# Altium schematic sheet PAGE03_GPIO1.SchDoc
size 381 x 304 mm; SheetNumber: 4; SheetTotal: 28
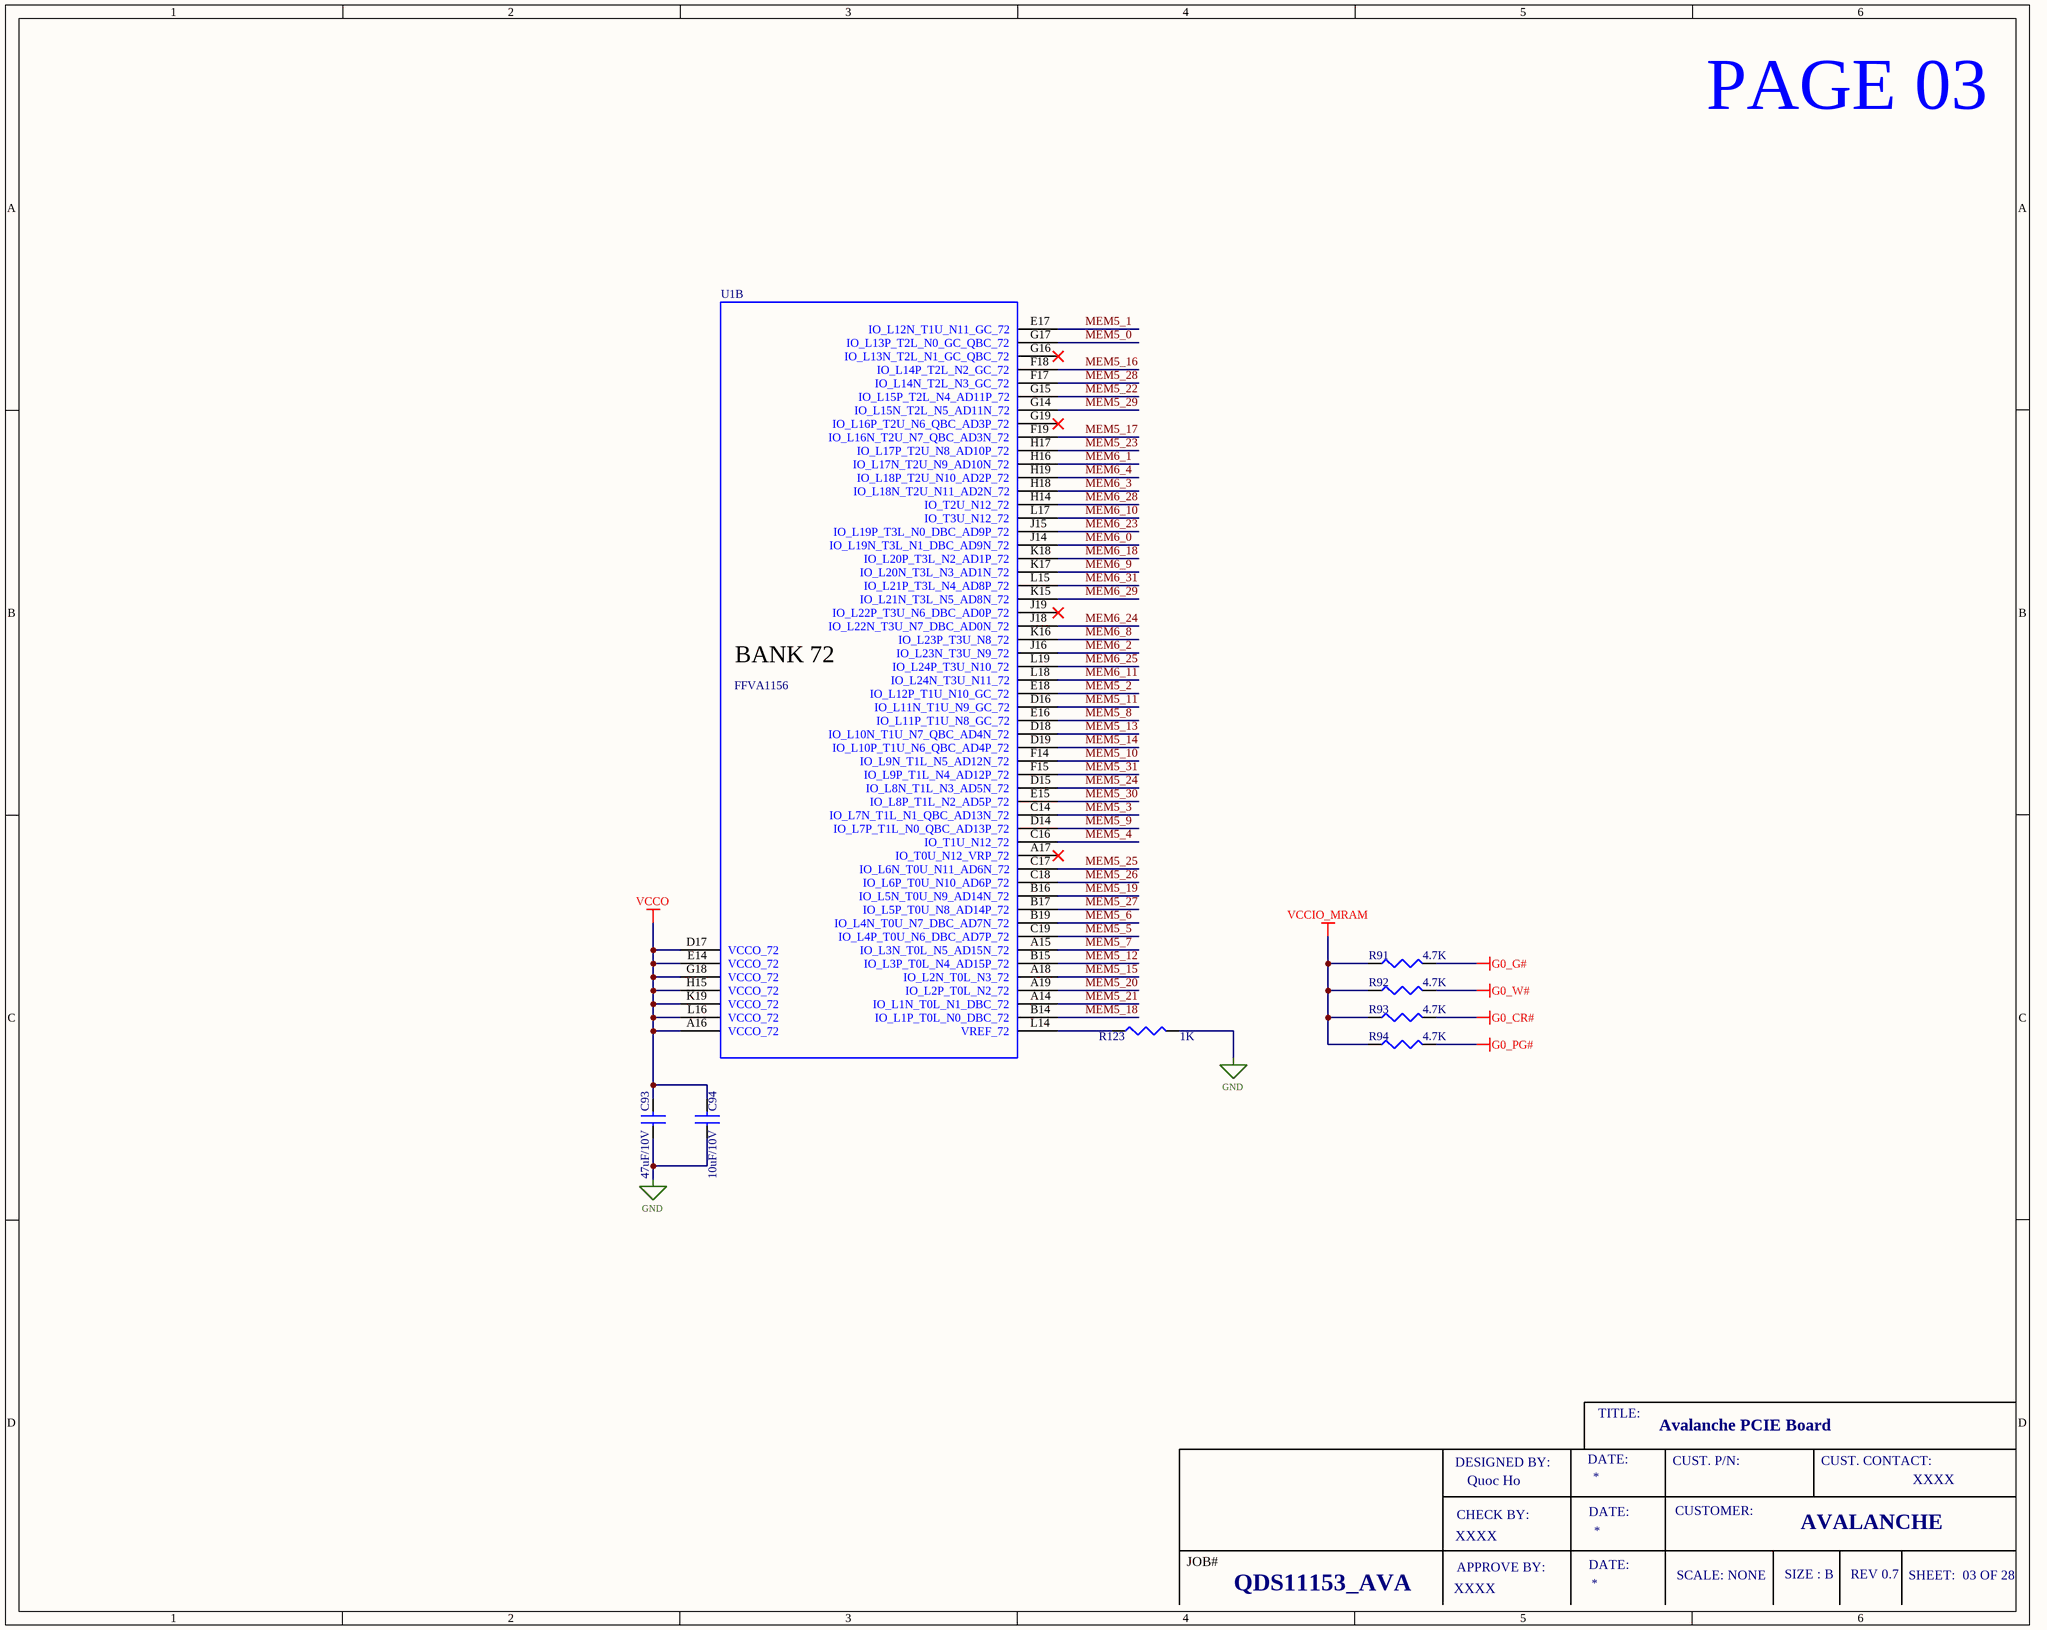
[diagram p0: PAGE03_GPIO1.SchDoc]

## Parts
C93  47uF/10V  [CN_0805]
C94  10uF/10V  [CN_0402]
R91  4.7K  [RN_0402]
R92  4.7K  [RN_0402]
R93  4.7K  [RN_0402]
R94  4.7K  [RN_0402]
R123  1K  [RN_0402]
U1  FFVA1156  [FFVA1156]  (part B of 25)

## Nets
G0_CR#: R93.2
G0_G#: R91.2
G0_PG#: R94.2
G0_W#: R92.2
GND: C93.1 C94.1 R123.2
VCCIO_MRAM: R91.1 R92.1 R93.1 R94.1
VCCO: C93.2 C94.2 U1.A16(VCCO_72) U1.D17(VCCO_72) U1.E14(VCCO_72) U1.G18(VCCO_72) U1.H15(VCCO_72) U1.K19(VCCO_72) U1.L16(VCCO_72)
MEM5_0: U1.G17(IO_L13P_T2L_N0_GC_QBC_72)
MEM5_1: U1.E17(IO_L12N_T1U_N11_GC_72)
MEM5_2: U1.E18(IO_L12P_T1U_N10_GC_72)
MEM5_3: U1.C14(IO_L7N_T1L_N1_QBC_AD13N_72)
MEM5_4: U1.C16(IO_T1U_N12_72)
MEM5_5: U1.C19(IO_L4P_T0U_N6_DBC_AD7P_72)
MEM5_6: U1.B19(IO_L4N_T0U_N7_DBC_AD7N_72)
MEM5_7: U1.A15(IO_L3N_T0L_N5_AD15N_72)
MEM5_8: U1.E16(IO_L11P_T1U_N8_GC_72)
MEM5_9: U1.D14(IO_L7P_T1L_N0_QBC_AD13P_72)
MEM5_10: U1.F14(IO_L9N_T1L_N5_AD12N_72)
MEM5_11: U1.D16(IO_L11N_T1U_N9_GC_72)
MEM5_12: U1.B15(IO_L3P_T0L_N4_AD15P_72)
MEM5_13: U1.D18(IO_L10N_T1U_N7_QBC_AD4N_72)
MEM5_14: U1.D19(IO_L10P_T1U_N6_QBC_AD4P_72)
MEM5_15: U1.A18(IO_L2N_T0L_N3_72)
MEM5_16: U1.F18(IO_L14P_T2L_N2_GC_72)
MEM5_17: U1.F19(IO_L16N_T2U_N7_QBC_AD3N_72)
MEM5_18: U1.B14(IO_L1P_T0L_N0_DBC_72)
MEM5_19: U1.B16(IO_L5N_T0U_N9_AD14N_72)
MEM5_20: U1.A19(IO_L2P_T0L_N2_72)
MEM5_21: U1.A14(IO_L1N_T0L_N1_DBC_72)
MEM5_22: U1.G15(IO_L15P_T2L_N4_AD11P_72)
MEM5_23: U1.H17(IO_L17P_T2U_N8_AD10P_72)
MEM5_24: U1.D15(IO_L8N_T1L_N3_AD5N_72)
MEM5_25: U1.C17(IO_L6N_T0U_N11_AD6N_72)
MEM5_26: U1.C18(IO_L6P_T0U_N10_AD6P_72)
MEM5_27: U1.B17(IO_L5P_T0U_N8_AD14P_72)
MEM5_28: U1.F17(IO_L14N_T2L_N3_GC_72)
MEM5_29: U1.G14(IO_L15N_T2L_N5_AD11N_72)
MEM5_30: U1.E15(IO_L8P_T1L_N2_AD5P_72)
MEM5_31: U1.F15(IO_L9P_T1L_N4_AD12P_72)
MEM6_0: U1.J14(IO_L19N_T3L_N1_DBC_AD9N_72)
MEM6_1: U1.H16(IO_L17N_T2U_N9_AD10N_72)
MEM6_2: U1.J16(IO_L23N_T3U_N9_72)
MEM6_3: U1.H18(IO_L18N_T2U_N11_AD2N_72)
MEM6_4: U1.H19(IO_L18P_T2U_N10_AD2P_72)
MEM6_8: U1.K16(IO_L23P_T3U_N8_72)
MEM6_9: U1.K17(IO_L20N_T3L_N3_AD1N_72)
MEM6_10: U1.L17(IO_T3U_N12_72)
MEM6_11: U1.L18(IO_L24N_T3U_N11_72)
MEM6_18: U1.K18(IO_L20P_T3L_N2_AD1P_72)
MEM6_23: U1.J15(IO_L19P_T3L_N0_DBC_AD9P_72)
MEM6_24: U1.J18(IO_L22N_T3U_N7_DBC_AD0N_72)
MEM6_25: U1.L19(IO_L24P_T3U_N10_72)
MEM6_28: U1.H14(IO_T2U_N12_72)
MEM6_29: U1.K15(IO_L21N_T3L_N5_AD8N_72)
MEM6_31: U1.L15(IO_L21P_T3L_N4_AD8P_72)
NetR123_1: R123.1 U1.L14(VREF_72)

Not connected (* = marked no-connect by the designer): U1 A17(IO_T0U_N12_VRP_72)* G16(IO_L13N_T2L_N1_GC_QBC_72)* G19(IO_L16P_T2U_N6_QBC_AD3P_72)* J19(IO_L22P_T3U_N6_DBC_AD0P_72)*

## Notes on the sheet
- PAGE 03
- (near U1) BANK 72
- TITLE:
- Avalanche PCIE Board
- DESIGNED BY:
- CHECK BY:
- Quoc Ho
- DATE:
- CUST. P/N:
- CUSTOMER:
- CUST. CONTACT:
- XXXX
- JOB#
- APPROVE BY:
- SCALE: NONE
- SIZE : B
- AVALANCHE
- REV 0.7
- SHEET:  03 OF 28
- QDS11153_AVA

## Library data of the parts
C93 = CAP: CAP CER 47UF 10V X5R 0805; Manufacturer: Murata Electronics; Manufacturer Part Number: GRM21BR61A476ME15K
C94 = CAP: CAP CER 10UF 10V X5R 0402; Manufacturer Part Number: GRM155R61A106ME11D; Manufacturer: Murata Electronics
R91-R94 = RES: RES 4.7K OHM 1% 1/16W 0402; Manufacturer Part Number: RC0402FR-134K7L; Manufacturer: YAGEO
R123 = RES: RES 1K OHM 1% 1/16W 0402; Manufacturer Part Number: RC0402FR-131KL; Manufacturer: YAGEO
U1 = FFVA1156: IC FPGA 516 I/O 1156FCBGA; Manufacturer Part Number: XCKU15P-1FFVA1156E; Manufacturer: AMD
